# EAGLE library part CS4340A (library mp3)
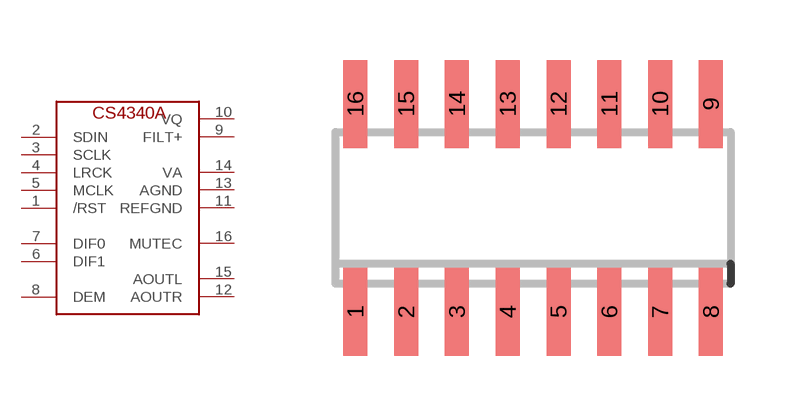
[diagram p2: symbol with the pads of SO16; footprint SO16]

Designator prefix -

## CS4340A  [SO16]
1  /RST  in
2  SDIN  in
3  SCLK  in
4  LRCK  in
5  MCLK  in
6  DIF1  in
7  DIF0  in
8  DEM  in
9  FILT+  out
10  VQ  out
11  REFGND  pwr
12  AOUTR  out
13  AGND  pwr
14  VA  pwr
15  AOUTL  out
16  MUTEC  out

## Footprint SO16 (pad centres in mm)
smd 0.6 x 2.2: 1 -4.445,-2.6; 2 -3.175,-2.6; 3 -1.905,-2.6; 4 -0.635,-2.6; 5 0.635,-2.6; 6 1.905,-2.6; 7 3.175,-2.6; 8 4.445,-2.6; 9 4.445,2.6; 10 3.175,2.6; 11 1.905,2.6; 12 0.635,2.6; 13 -0.635,2.6; 14 -1.905,2.6; 15 -3.175,2.6; 16 -4.445,2.6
